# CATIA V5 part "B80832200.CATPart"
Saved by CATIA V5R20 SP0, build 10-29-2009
Part number: B80832200
Revision: 3
Definition: design
Nomenclature: B80832200
Source: made
Description: NOT SPECIFIED
Bounding box of the stored display mesh (mm): x -18.312 to 18.312, y -18.5 to 18.5, z 0 to 200
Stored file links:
  C:\Users\Raffaele\Desktop\3D X SITO CF\BOLEX\4-PILLAR REF 808\B80832200.CATPart
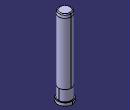
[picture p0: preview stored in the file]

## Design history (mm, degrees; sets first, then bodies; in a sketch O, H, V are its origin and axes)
Body1 "MANIFOLD_SOLID_BREP #450" (main body)
  Solid1: solid without history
